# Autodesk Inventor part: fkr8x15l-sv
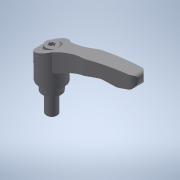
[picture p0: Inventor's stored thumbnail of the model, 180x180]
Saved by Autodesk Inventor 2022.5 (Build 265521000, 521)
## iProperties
Created: 2017-09
Part Number: fkr8x15l-sv
Material: 一般
Document SubType Name: Modeling
Designer: imaocorp
Density: 1 g/cm^3
Appearance: 既定
Author: imaocorp
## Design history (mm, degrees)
node "fkr8x15l-sv.x_t1"
node "fkr8x15l-sv"
node "Base1"
